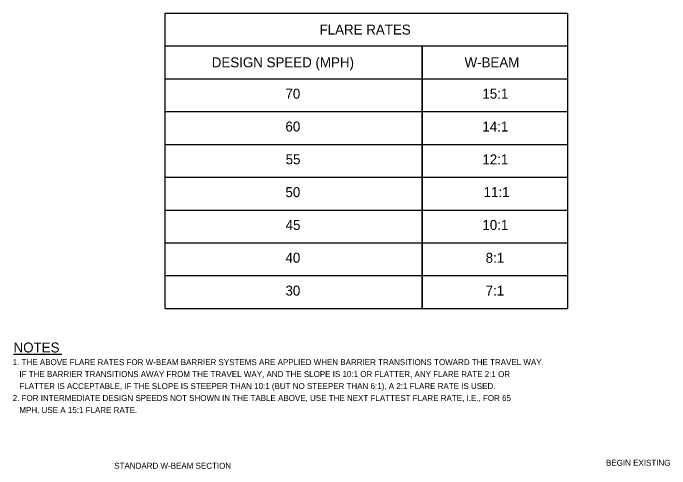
# Model space of a CAD drawing. Extents: x 12.39 to 19.62, y 5.98 to 15.84.
# Drawn here: x 12.39 to 18.98, y 11.26 to 15.84 of the extents above; entities that cross this region are included whole.
import ezdxf

# ---------------------------------------------------------------- set-up
doc = ezdxf.new("R2010")
doc.units = 0
doc.layers.add('DETL-NOTE', color=7, linetype='Continuous')
doc.layers.add('DETL-TITL', color=7, linetype='Continuous')

msp = doc.modelspace()

# ---------------------------------------------------------------- linework, layer by layer
at = {"layer": 'DETL-NOTE'}
for p, q in [((16.4965, 15.5082), (16.4965, 15.179)), ((13.916, 12.8741), (17.9514, 12.8741)), ((12.3966, 12.4152), (12.8814, 12.4152))]:
    msp.add_line(p, q, dxfattribs=at)
for points in [[(13.916, 15.5082), (13.916, 15.8375), (17.9514, 15.8375), (17.9514, 15.5082)], [(13.916, 15.179), (13.916, 15.5082), (16.4965, 15.5082), (16.4965, 15.179), (16.4965, 15.5082), (17.9514, 15.5082), (17.9514, 15.179)], [(13.916, 14.8497), (13.916, 15.179), (16.4965, 15.179), (16.4965, 14.8497), (16.4965, 15.179), (17.9514, 15.179), (17.9514, 14.8497)], [(13.916, 14.5204), (13.916, 14.8497), (16.4965, 14.8497), (16.4965, 14.5204), (16.4965, 14.8497), (17.9514, 14.8497), (17.9514, 14.5204)], [(13.916, 14.1912), (13.916, 14.5204), (16.4965, 14.5204), (16.4965, 14.1912), (16.4965, 14.5204), (17.9514, 14.5204), (17.9514, 14.1912)], [(13.916, 13.8619), (13.916, 14.1912), (16.4965, 14.1912), (16.4965, 13.8619), (16.4965, 14.1912), (17.9514, 14.1912), (17.9514, 13.8619)], [(13.916, 13.5327), (13.916, 13.8619), (16.4965, 13.8619), (16.4965, 13.5327), (16.4965, 13.8619), (17.9514, 13.8619), (17.9514, 13.5327)], [(13.916, 13.2034), (13.916, 13.5327), (16.4965, 13.5327), (16.4965, 13.2034), (16.4965, 13.5327), (17.9514, 13.5327), (17.9514, 13.2034)], [(13.916, 12.8741), (13.916, 13.2034), (16.4965, 13.2034), (16.4965, 12.8741), (16.4965, 13.2034), (17.9514, 13.2034), (17.9514, 12.8741)]]:
    msp.add_lwpolyline(points, dxfattribs=at)

# ---------------------------------------------------------------- texts
for s, height, p in [('NOTES', 0.1, (12.3966, 12.4323)), ('BEGIN EXISTING ', 0.06, (18.3393, 11.2952)), ('STANDARD W-BEAM SECTION', 0.06, (13.4067, 11.2652))]:
    msp.add_text(s, height=height, rotation=360, dxfattribs=at).set_placement(p)
for s, p in [('1. THE ABOVE FLARE RATES FOR W-BEAM BARRIER SYSTEMS ARE APPLIED WHEN BARRIER TRANSITIONS TOWARD THE TRAVEL WAY.', (12.3882, 12.3052)), ('   IF THE BARRIER TRANSITIONS AWAY FROM THE TRAVEL WAY, AND THE SLOPE IS 10:1 OR FLATTER, ANY FLARE RATE 2:1 OR', (12.3882, 12.1852)), ('   FLATTER IS ACCEPTABLE, IF THE SLOPE IS STEEPER THAN 10:1 (BUT NO STEEPER THAN 6:1), A 2:1 FLARE RATE IS USED.', (12.3882, 12.0652)), ('2. FOR INTERMEDIATE DESIGN SPEEDS NOT SHOWN IN THE TABLE ABOVE, USE THE NEXT FLATTEST FLARE RATE, I.E., FOR 65', (12.3882, 11.9452)), ('   MPH, USE A 15:1 FLARE RATE.', (12.3882, 11.8252))]:
    msp.add_text(s, height=0.06, dxfattribs=at).set_placement(p)
at = {"layer": 'DETL-TITL'}
for s, p in [('FLARE RATES', (15.466, 15.6224)), ('DESIGN SPEED (MPH)', (14.3849, 15.2934)), ('W-BEAM', (16.9205, 15.2934)), ('70', (15.1238, 14.979)), ('15:1', (17.0991, 14.979)), ('60', (15.1238, 14.6497)), ('14:1', (17.0991, 14.6497)), ('55', (15.1256, 14.3204)), ('12:1', (17.0991, 14.3204)), ('50', (15.1238, 13.9912)), ('11:1', (17.1112, 13.9912)), ('45', (15.1256, 13.6619)), ('10:1', (17.0991, 13.6619)), ('40', (15.1238, 13.3327)), ('8:1', (17.1321, 13.3327)), ('30', (15.1238, 13.0034)), ('7:1', (17.1321, 13.0034))]:
    msp.add_text(s, height=0.1, dxfattribs=at).set_placement(p)

doc.saveas('drawing.dxf')
